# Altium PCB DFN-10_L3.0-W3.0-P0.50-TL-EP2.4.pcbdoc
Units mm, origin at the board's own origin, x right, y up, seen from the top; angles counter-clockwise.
Board outline 16.44 x 15.9 mm, 2 copper layers (Top Layer, Bottom Layer), stack 0 mm thick; 1 components, 0 nets, 11 pads, 0 vias.
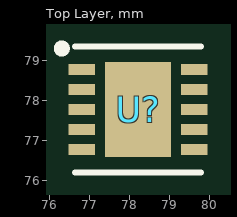
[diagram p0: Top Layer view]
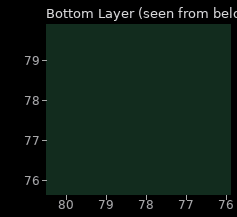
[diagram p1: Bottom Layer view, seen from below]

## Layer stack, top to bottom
Top Layer: signal copper (thickness not stored)
Bottom Layer: signal copper (thickness not stored)

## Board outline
86.295,69.85 69.85,69.85 69.85,85.75 86.295,85.75

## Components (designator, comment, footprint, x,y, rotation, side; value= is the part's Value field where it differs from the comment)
U? "" DFN-10_L3.0-W3.0-P0.50-TL-EP2.4 78.205,77.776 r0 top

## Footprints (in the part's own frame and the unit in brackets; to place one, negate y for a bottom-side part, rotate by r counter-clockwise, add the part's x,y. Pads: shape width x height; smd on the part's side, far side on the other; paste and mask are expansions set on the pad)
DFN-10_L3.0-W3.0-P0.50-TL-EP2.4 [mm]
  rect 0.665x0.28 smd: 1(-1.407,1) 2(-1.407,0.5) 3(-1.407,0) 4(-1.407,-0.5) 5(-1.407,-1) 6(1.407,-1) 7(1.407,-0.5) 8(1.407,0) 9(1.407,0.5) 10(1.407,1)
  rect 1.64x2.38 smd: 11(0,0)
  silkscreen extent -2,-1.58 1.58,1.62

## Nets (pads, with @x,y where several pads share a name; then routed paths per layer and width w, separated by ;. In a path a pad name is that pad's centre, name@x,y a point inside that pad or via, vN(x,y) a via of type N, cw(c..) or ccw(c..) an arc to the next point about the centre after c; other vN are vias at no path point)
pads on no net: U?.1 U?.2 U?.3 U?.4 U?.5 U?.6 U?.7 U?.8 U?.9 U?.10 U?.11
